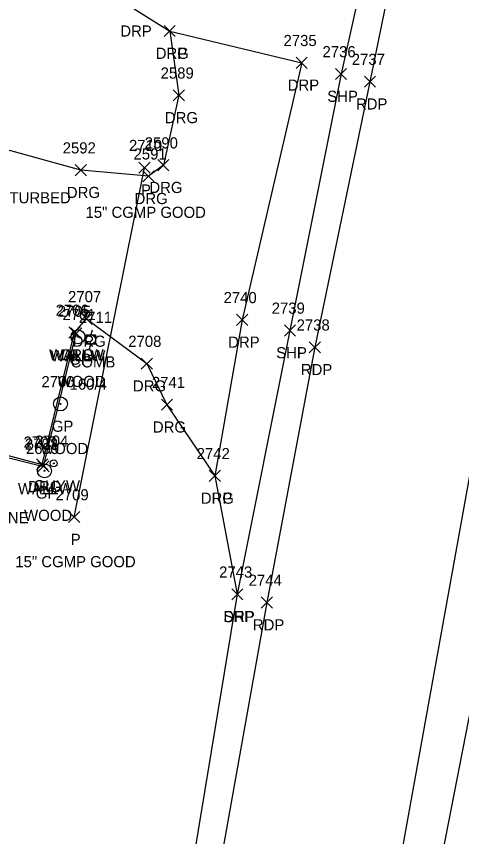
# Model space of a CAD drawing. Extents: x 1443071 to 1445292, y 614024 to 622563.
# Drawn here: x 1444039.9 to 1444119.8, y 620180.3 to 620327.5 of the extents above; entities that cross this region are included whole.
import ezdxf

# ---------------------------------------------------------------- set-up
doc = ezdxf.new("R2010")
doc.units = 0
for name, color, linetype in [('D_A', 7, 'Continuous'), ('D_C', 7, 'Continuous'), ('D_I', 7, 'Continuous'), ('D_TIC', 7, 'Continuous'), ('DCP', 7, 'Continuous'), ('L_A', 7, 'Continuous'), ('L_I', 7, 'Continuous'), ('L_TIC', 7, 'Continuous'), ('LW', 7, 'Continuous'), ('M_C', 7, 'Continuous'), ('P_A', 7, 'Continuous'), ('P_I', 7, 'Continuous'), ('P_TIC', 7, 'Continuous'), ('PET', 7, 'Continuous'), ('PSP', 7, 'Continuous'), ('R_A', 7, 'Continuous'), ('R_C', 7, 'Continuous'), ('R_I', 7, 'Continuous'), ('R_TIC', 7, 'Continuous'), ('RDG', 7, 'Continuous'), ('RDP', 7, 'Continuous'), ('RGP', 7, 'Continuous'), ('U_A', 7, 'Continuous'), ('U_C', 7, 'Continuous'), ('U_I', 7, 'Continuous'), ('UP', 7, 'Continuous'), ('UPGW', 7, 'Continuous')]:
    doc.layers.add(name, color=color, linetype=linetype)

msp = doc.modelspace()

# ---------------------------------------------------------------- linework, layer by layer
at = {"layer": 'D_TIC'}
for points in [[(1444061.9, 620299.32), (1444063.9, 620301.32)], [(1444063.9, 620299.32), (1444061.9, 620301.32)], [(1444049.29, 620236.63), (1444051.29, 620238.63)], [(1444051.29, 620236.63), (1444049.29, 620238.63)]]:
    msp.add_lwpolyline(points, dxfattribs=at)
at = {"layer": 'DCP'}
msp.add_lwpolyline([(1444050.29, 620237.63), (1444062.9, 620300.32)], dxfattribs=at)
at = {"layer": 'L_TIC'}
for points in [[(1444049.35, 620269.75), (1444051.35, 620271.75)], [(1444051.35, 620269.75), (1444049.35, 620271.75)], [(1444049.66, 620269.57), (1444051.66, 620271.57)], [(1444051.66, 620269.57), (1444049.66, 620271.57)], [(1444043.78, 620245.72), (1444045.78, 620247.72)], [(1444045.78, 620245.72), (1444043.78, 620247.72)]]:
    msp.add_lwpolyline(points, dxfattribs=at)
at = {"layer": 'LW'}
msp.add_lwpolyline([(1444034.21, 620249.34), (1444044.78, 620246.72), (1444050.66, 620270.57), (1444050.35, 620270.75)], dxfattribs=at)
at = {"layer": 'P_TIC'}
for points in [[(1444097.18, 620316.14), (1444099.18, 620318.14)], [(1444099.18, 620316.14), (1444097.18, 620318.14)], [(1444102.37, 620314.76), (1444104.37, 620316.76)], [(1444104.37, 620314.76), (1444102.37, 620316.76)], [(1444088.01, 620270.12), (1444090.01, 620272.12)], [(1444090.01, 620270.12), (1444088.01, 620272.12)], [(1444092.47, 620267.1), (1444094.47, 620269.1)], [(1444094.47, 620267.1), (1444092.47, 620269.1)], [(1444078.56, 620222.77), (1444080.56, 620224.77)], [(1444080.56, 620222.77), (1444078.56, 620224.77)], [(1444083.86, 620221.29), (1444085.86, 620223.29)], [(1444085.86, 620221.29), (1444083.86, 620223.29)]]:
    msp.add_lwpolyline(points, dxfattribs=at)
at = {"layer": 'PET'}
for points in [[(1444393.99, 621275.61), (1444360.23, 621155.32), (1444345.74, 621103.98), (1444299.41, 620941.8), (1444273.27, 620844.52), (1444244.09, 620730.97), (1444221.37, 620651.37), (1444196.75, 620548.06), (1444177.44, 620486.23), (1444161.6, 620423.84), (1444143.45, 620356.38), (1444122.97, 620254.68), (1444105.94, 620160.17), (1444094.56, 620089.52), (1444083.91, 620011.71), (1444077.6, 619958.52), (1444073.05, 619913.75)], [(1444350.41, 621238.76), (1444319.14, 621126.97), (1444291.55, 621028.33), (1444258.02, 620908.98), (1444225.45, 620794.19), (1444210.22, 620737.59), (1444176.75, 620619.09), (1444153.1, 620523.45), (1444139.28, 620467.17), (1444131.97, 620435.45), (1444113.12, 620363.38), (1444103.37, 620315.76), (1444093.47, 620268.1), (1444084.86, 620222.29), (1444073.72, 620159.9), (1444065.08, 620092.83), (1444054.27, 620016.44), (1444048.57, 619960.86), (1444043.42, 619916.17), (1444073.05, 619913.75)]]:
    msp.add_lwpolyline(points, dxfattribs=at)
at = {"layer": 'PSP'}
for points in [[(1444228.91, 620648.98), (1444202.76, 620547.52), (1444186.16, 620483.96), (1444170.45, 620422.38), (1444153.07, 620354.47), (1444132.16, 620257.26), (1444128.32, 620238.3), (1444112.75, 620158.8), (1444100.76, 620089.32), (1444087.94, 620010.71), (1444079.9, 619958.71), (1444074.06, 619920.41), (1444074.5, 619920), (1444074.51, 619919.99), (1444073.05, 619913.75)], [(1444173.15, 620620.17), (1444162.97, 620582.35), (1444145.76, 620516.18), (1444133.67, 620469.15), (1444125.56, 620436.17), (1444114.52, 620389.82), (1444108.73, 620364.47), (1444098.18, 620317.14), (1444089.01, 620271.12), (1444079.56, 620223.77), (1444069.05, 620160.45), (1444059.79, 620093.6), (1444051.39, 620014.62), (1444046.92, 619961.11), (1444044.18, 619924.22), (1444043.48, 619922.84), (1444043.42, 619916.17)]]:
    msp.add_lwpolyline(points, dxfattribs=at)
at = {"layer": 'R_TIC'}
for points in [[(1444066.43, 620323.85), (1444068.43, 620325.85)], [(1444068.43, 620323.85), (1444066.43, 620325.85)], [(1444066.43, 620323.85), (1444068.43, 620325.85)], [(1444068.43, 620323.85), (1444066.43, 620325.85)], [(1444090.12, 620318.15), (1444092.12, 620320.15)], [(1444092.12, 620318.15), (1444090.12, 620320.15)], [(1444068.07, 620312.31), (1444070.07, 620314.31)], [(1444070.07, 620312.31), (1444068.07, 620314.31)], [(1444065.3, 620299.78), (1444067.3, 620301.78)], [(1444067.3, 620299.78), (1444065.3, 620301.78)], [(1444050.48, 620298.88), (1444052.48, 620300.88)], [(1444052.48, 620298.88), (1444050.48, 620300.88)], [(1444062.63, 620297.79), (1444064.63, 620299.79)], [(1444064.63, 620297.79), (1444062.63, 620299.79)], [(1444051.51, 620272.19), (1444053.51, 620274.19)], [(1444053.51, 620272.19), (1444051.51, 620274.19)], [(1444079.44, 620272.02), (1444081.44, 620274.02)], [(1444081.44, 620272.02), (1444079.44, 620274.02)], [(1444049.35, 620269.75), (1444051.35, 620271.75)], [(1444051.35, 620269.75), (1444049.35, 620271.75)], [(1444062.33, 620264.17), (1444064.33, 620266.17)], [(1444064.33, 620264.17), (1444062.33, 620266.17)], [(1444065.93, 620256.79), (1444067.93, 620258.79)], [(1444067.93, 620256.79), (1444065.93, 620258.79)], [(1444043.54, 620246.09), (1444045.54, 620248.09)], [(1444045.54, 620246.09), (1444043.54, 620248.09)], [(1444074.53, 620244.02), (1444076.53, 620246.02)], [(1444076.53, 620244.02), (1444074.53, 620246.02)], [(1444074.53, 620244.02), (1444076.53, 620246.02)], [(1444076.53, 620244.02), (1444074.53, 620246.02)], [(1444078.56, 620222.77), (1444080.56, 620224.77)], [(1444080.56, 620222.77), (1444078.56, 620224.77)]]:
    msp.add_lwpolyline(points, dxfattribs=at)
at = {"layer": 'RDG'}
for points in [[(1444067.43, 620324.85), (1444069.07, 620313.31), (1444066.3, 620300.78), (1444063.63, 620298.79), (1444051.48, 620299.88), (1444034.28, 620304.59), (1443998.41, 620326.25)], [(1444006.82, 620265.14), (1444009.31, 620263.64), (1444008.46, 620257.52), (1444034.32, 620249.74), (1444044.54, 620247.09), (1444050.35, 620270.75), (1444052.51, 620273.19), (1444063.33, 620265.17), (1444066.93, 620257.79), (1444075.53, 620245.02)]]:
    msp.add_lwpolyline(points, dxfattribs=at)
at = {"layer": 'RDP'}
msp.add_lwpolyline([(1444070.37, 620410.77), (1444058.23, 620410.82), (1444048.11, 620415.44), (1444048.14, 620371.68), (1444053.99, 620368.8), (1444056.05, 620336.57), (1444061.07, 620328.85), (1444067.43, 620324.85), (1444091.12, 620319.15), (1444080.44, 620273.02), (1444075.53, 620245.02), (1444079.56, 620223.77)], dxfattribs=at)
at = {"layer": 'RGP'}
for p, q in [((1444050.97, 620269.97), (1444050.97, 620269.97)), ((1444047.84, 620257.93), (1444047.84, 620257.93)), ((1444044.94, 620245.94), (1444044.94, 620245.94))]:
    msp.add_line(p, q, dxfattribs=at)
for centre, radius in [((1444050.97, 620269.97), 1.25), ((1444050.97, 620269.97), 0.0833), ((1444047.84, 620257.93), 1.25), ((1444047.84, 620257.93), 0.0833), ((1444044.94, 620245.94), 1.25), ((1444044.94, 620245.94), 0.0833)]:
    msp.add_circle(centre, radius, dxfattribs=at)
at = {"layer": 'UP'}
for p, q in [((1444053.51, 620271.15), (1444053.26, 620270.32)), ((1444052.43, 620268.65), (1444052.43, 620270.32)), ((1444052.43, 620270.32), (1444054.09, 620270.32)), ((1444053.26, 620269.48), (1444053.26, 620269.48)), ((1444054.09, 620270.32), (1444054.09, 620268.65)), ((1444054.09, 620268.65), (1444052.43, 620268.65)), ((1444053.01, 620267.82), (1444053.26, 620268.65))]:
    msp.add_line(p, q, dxfattribs=at)
msp.add_circle((1444053.26, 620269.48), 0.833, dxfattribs=at)
at = {"layer": 'UPGW'}
for radius in [0.625, 0.0833]:
    msp.add_circle((1444046.61, 620247.25), radius, dxfattribs=at)

# ---------------------------------------------------------------- texts
at = {"layer": 'D_A'}
for p in [(1444062.27, 620295.32), (1444049.67, 620232.63)]:
    msp.add_text('P', height=2, dxfattribs=at).set_placement(p)
at = {"layer": 'D_C'}
for p in [(1444052.32, 620291.32), (1444039.72, 620228.63)]:
    msp.add_text('15" CGMP GOOD', height=2, dxfattribs=at).set_placement(p)
at = {"layer": 'D_I'}
for s, p in [('2710', (1444060.12, 620303.32)), ('2709', (1444046.94, 620240.63))]:
    msp.add_text(s, height=2, dxfattribs=at).set_placement(p)
at = {"layer": 'L_A'}
for s, p in [('WALLW', (1444045.77, 620265.75)), ('WALLW', (1444046.08, 620265.57)), ('WALLW', (1444040.19, 620241.72)), ('STONE', (1444032.88, 620236.52))]:
    msp.add_text(s, height=2, dxfattribs=at).set_placement(p)
at = {"layer": 'L_I'}
for s, p in [('2706', (1444046.96, 620273.75)), ('2705', (1444047.32, 620273.57)), ('2702', (1444041.44, 620249.72))]:
    msp.add_text(s, height=2, dxfattribs=at).set_placement(p)
at = {"layer": 'M_C'}
msp.add_text('3/4 " REBAR BENT DISTURBED', height=2, dxfattribs=at).set_placement((1444010.23, 620293.93))
at = {"layer": 'P_A'}
for s, p in [('SHP', (1444095.71, 620312.14)), ('RDP', (1444100.86, 620310.76)), ('SHP', (1444086.55, 620266.12)), ('RDP', (1444090.96, 620263.1)), ('SHP', (1444077.09, 620218.77)), ('RDP', (1444082.35, 620217.29))]:
    msp.add_text(s, height=2, dxfattribs=at).set_placement(p)
at = {"layer": 'P_I'}
for s, p in [('2736', (1444094.86, 620320.14)), ('2737', (1444100.11, 620318.76)), ('2739', (1444085.74, 620274.12)), ('2738', (1444090.21, 620271.1)), ('2743', (1444076.3, 620226.77)), ('2744', (1444081.6, 620225.29))]:
    msp.add_text(s, height=2, dxfattribs=at).set_placement(p)
at = {"layer": 'R_A'}
for s, p in [('DRP', (1444058.56, 620323.85)), ('DRG', (1444064.92, 620319.85)), ('DRP', (1444064.92, 620319.85)), ('DRP', (1444088.61, 620314.15)), ('DRG', (1444066.56, 620308.31)), ('DRG', (1444048.97, 620294.88)), ('DRG', (1444063.78, 620295.78)), ('DRG', (1444061.12, 620293.79)), ('DRG', (1444050, 620268.19)), ('DRP', (1444077.93, 620268.02)), ('DRG', (1444047.84, 620265.75)), ('GP', (1444049.4, 620264.97)), ('DRG', (1444060.82, 620260.17)), ('GP', (1444046.27, 620252.93)), ('DRG', (1444064.41, 620252.79)), ('DRG', (1444042.03, 620242.09)), ('GP', (1444043.38, 620240.94)), ('DRG', (1444073.01, 620240.02)), ('DRP', (1444073.01, 620240.02)), ('DRP', (1444077.05, 620218.77))]:
    msp.add_text(s, height=2, dxfattribs=at).set_placement(p)
at = {"layer": 'R_C'}
for p in [(1444047.32, 620260.97), (1444044.19, 620248.93), (1444041.3, 620236.94)]:
    msp.add_text('WOOD', height=2, dxfattribs=at).set_placement(p)
at = {"layer": 'R_I'}
for s, p in [('2735', (1444087.86, 620322.15)), ('2589', (1444065.8, 620316.31)), ('2590', (1444062.95, 620303.78)), ('2592', (1444048.22, 620302.88)), ('2591', (1444060.94, 620301.79)), ('2707', (1444049.18, 620276.19)), ('2740', (1444077.1, 620276.02)), ('2706', (1444046.96, 620273.75)), ('2701', (1444048.2, 620272.97)), ('2708', (1444059.99, 620268.17)), ('2700', (1444044.41, 620260.93)), ('2741', (1444064.23, 620260.79)), ('2703', (1444041.2, 620250.09)), ('2699', (1444041.63, 620248.94)), ('2742', (1444072.27, 620248.02)), ('2742', (1444072.27, 620248.02)), ('2743', (1444076.3, 620226.77))]:
    msp.add_text(s, height=2, dxfattribs=at).set_placement(p)
at = {"layer": 'U_A'}
for s, p in [('COMB', (1444049.65, 620264.48)), ('GUYW', (1444043.01, 620242.25))]:
    msp.add_text(s, height=2, dxfattribs=at).set_placement(p)
at = {"layer": 'U_C'}
msp.add_text('160/4', height=2, dxfattribs=at).set_placement((1444049.46, 620260.48))
at = {"layer": 'U_I'}
for s, p in [('2711', (1444051.13, 620272.48)), ('2704', (1444043.28, 620250.25))]:
    msp.add_text(s, height=2, dxfattribs=at).set_placement(p)

doc.saveas('drawing.dxf')
